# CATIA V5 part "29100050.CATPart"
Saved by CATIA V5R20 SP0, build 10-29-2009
Part number: 29100050
Definition: NONE
Nomenclature: 29100050
Source: Unknown
Description: 29100050
Bounding box of the stored display mesh (mm): x -25 to 44.548, y -64 to 98.548, z -54 to 54
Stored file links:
  C:\Users\Utente\Desktop\IO LAVORO\3D X SITO CF\X SITO\PLASTICA\RF1\29100050.CATPart
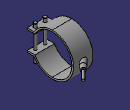
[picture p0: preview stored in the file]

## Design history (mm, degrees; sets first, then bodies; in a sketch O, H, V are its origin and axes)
Body1 "29100050" (main body)
  Solid1: solid without history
